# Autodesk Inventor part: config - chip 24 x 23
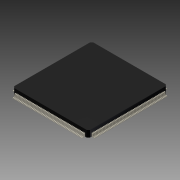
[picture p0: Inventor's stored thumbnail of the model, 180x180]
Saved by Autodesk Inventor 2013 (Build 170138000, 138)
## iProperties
Company: Autodesk Inc.
Created: 2005-12
Part Number: config - chip 24 x 23
Document SubType Name: Modeling
Designer: Autodesk Inc.
Stock Number: config - chip 24 x 23
Density: 1 g/cm^3
Mass: 1.1261 g
Surface Area: 15.9357 cm^2
Volume: 1.1261 cm^3
Material: Allgemein
Title: Personal Computer
Author: Autodesk Inc.
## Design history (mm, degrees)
sketch "Sketch1"
  geometry: L1 (0, 16.8)-(0, -16.8) reference; L2 (-16.1, 0)-(16.1, 0) reference; L3 (-11.5, 12)-(11.5, 12); L4 (11.5, 12)-(11.5, -12); L5 (11.5, -12)-(-11.5, -12); L6 (-11.5, -12)-(-11.5, 12)
  constraints: 8 end point, 2 parallel, 1 horizontal, 1 perpendicular, 2 other
  dimensions: "d0" = 23 distance of L3.start L3.end; "d1" = 24 distance of L5.end L3.start
extrude "Extrusion1" new body sketch "Sketch1" distance "d2" = 2; taper "d3" = 0 deg
workplane "Work Plane1"
sketch "Sketch3"
  geometry: L1 (23, 0)-(23, 2) reference; L2 (23, 0)-(0, 0) reference; L3 (23, 0)-(24.221, 0); L4 (23, 1)-(23.312, 1); L5 (23.411, 0.912)-(23.489, 0.288); L6 (23.588, 0.2)-(23.85, 0.2); L7 (24, 0.05)-(24, 0); L8 (23, 0)-(24, 0); L9 (23, 0)-(23, 1); A1 r 0.1 centre (23.312, 0.9) between (23.411, 0.912) and (23.312, 1); A2 r 0.1 centre (23.588, 0.3) between (23.489, 0.288) and (23.588, 0.2); A3 r 0.15 centre (23.85, 0.05) between (24, 0.05) and (23.85, 0.2); 3 further points
  constraints: 14 end point, 7 point on line, 6 point on circle, 6 tangent, 3 centre point, 3 collinear, 2 parallel, 1 equal radius, 1 midpoint, 1 perpendicular
  dimensions: "d13" = 1 distance between parallel lines of L9 L7; "d14" = 0.4 distance of L4.start point (23.4, 1); "d15" = 0.2 distance of point (24, 0.2) L7.end; "d16" = 0.5 distance of point (23.5, 0.2) point (24, 0.2); "d17" = 0.1 radius of A1; "d18" = 0.15 radius of A3
extrude "Extrusion3" join sketch "Sketch3" distance "d19" = 0.2; taper "d20" = 0 deg
mirror "Mirror3"
workplane "Work Plane3"
sketch "Sketch5"
  geometry: L1 (2, 0)-(0, 0) reference; L2 (2, 1)-(2, 0) reference; L3 (2, 0)-(2, -1.562); L4 (1, 0)-(1, -0.312); L5 (1.088, -0.411)-(1.712, -0.489); L6 (1.8, -0.588)-(1.8, -0.85); L7 (1.95, -1)-(2, -1); L8 (2, 0)-(2, -1); L9 (1, 0)-(2, 0); A1 r 0.15 centre (1.95, -0.85) between (1.8, -0.85) and (1.95, -1); A2 r 0.1 centre (1.1, -0.312) between (1, -0.312) and (1.088, -0.411); A3 r 0.1 centre (1.7, -0.588) between (1.8, -0.588) and (1.712, -0.489); 3 further points
  constraints: 14 end point, 7 point on line, 6 point on circle, 6 tangent, 3 centre point, 3 collinear, 2 parallel, 1 equal radius, 1 midpoint, 1 perpendicular
  dimensions: "d25" = 0.2 distance of point (1.8, -1) L7.end; "d26" = 0.5 distance of point (1.8, -0.5) point (1.8, -1); "d27" = 0.4 distance of L4.start point (1, -0.4); "d28" = 1 distance between parallel lines of L1 L7; "d29" = 0.15 radius of A1; "d30" = 0.1 radius of A2
extrude "Extrusion4" join sketch "Sketch5" distance "d31" = 0.2; taper "d32" = 0 deg
mirror "Mirror4"
chamfer "Chamfer1" distance "d36" = 0.5; stored, may be unused: second distance "d37" = 2, angle "d38" = 45 deg
body "Solid1"
pattern_linear "Rectangular Pattern2" dims "d23" = 21.8
pattern_linear "Rectangular Pattern3" dims "d35" = 20.8
other parameters: "d4" = -1, "d24" = -1
